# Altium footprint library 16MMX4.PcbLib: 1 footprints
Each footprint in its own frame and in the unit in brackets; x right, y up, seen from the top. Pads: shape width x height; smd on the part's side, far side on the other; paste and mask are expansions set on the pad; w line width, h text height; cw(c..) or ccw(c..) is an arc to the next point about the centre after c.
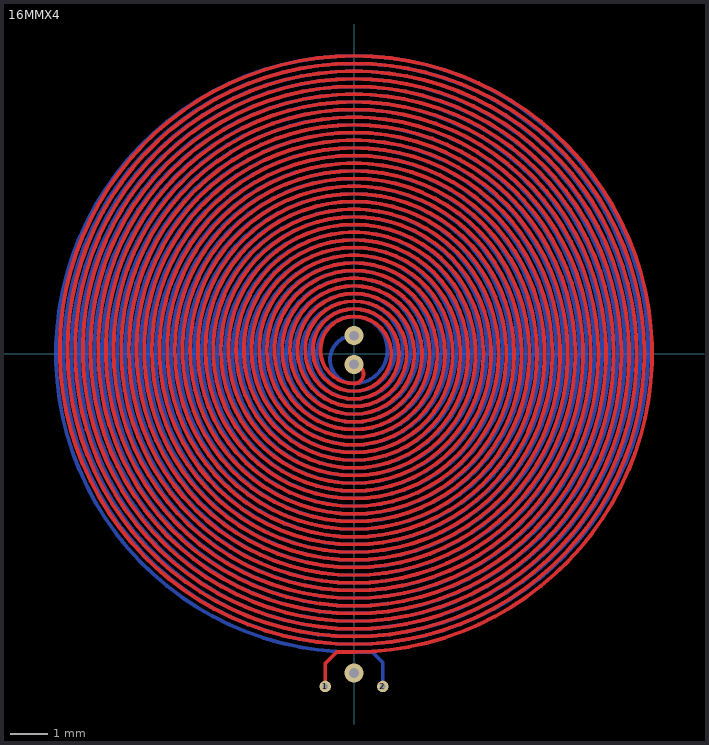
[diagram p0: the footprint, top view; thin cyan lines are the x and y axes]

## 16MMX4 [mil] "4,4,70,20,10,35"
pads (2):
  round 12 hole 6: 1(-30,-347) 2(30,-347)
via 0,19 diameter 20 hole 10
via 0,-11 diameter 20 hole 10
via 0,-333 diameter 20 hole 10
Top Layer:
  lines w4: -30,-347 -30,-344.65 ; -30,-344.65 -30,-344.25 ; -30,-344.65 -30,-344.25 ; -30,-344.25 -30,-323 ; -30,-344.25 -30,-323 ; -30,-323 -18,-311 ; -18,-311 0,-311 ; -18,-311 0,-311 ; 0,-311 ccw(c0,0) 0,311 ; 0,-311 ccw(c0,0) 0,311 ; 0,-311 0,-311 ; 0,-303 cw(c0,4) 0,311 ; 0,-303 ccw(c0,0) 0,303 ; 0,-303 ccw(c0,0) 0,303 ; 0,-303 cw(c0,4) 0,311 ; 0,-295 cw(c0,4) 0,303 ; 0,-295 ccw(c0,0) 0,295 ; 0,-295 ccw(c0,0) 0,295 ; 0,-295 cw(c0,4) 0,303 ; 0,-287 cw(c0,4) 0,295 ; 0,-287 ccw(c0,0) 0,287 ; 0,-287 ccw(c0,0) 0,287 ; 0,-287 cw(c0,4) 0,295 ; 0,-279 cw(c0,4) 0,287 ; 0,-279 ccw(c0,0) 0,279 ; 0,-279 ccw(c0,0) 0,279 ; 0,-279 cw(c0,4) 0,287 ; 0,-271 cw(c0,4) 0,279 ; 0,-271 ccw(c0,0) 0,271 ; 0,-271 ccw(c0,0) 0,271 ; 0,-271 cw(c0,4) 0,279 ; 0,-263 cw(c0,4) 0,271 ; 0,-263 ccw(c0,0) 0,263 ; 0,-263 ccw(c0,0) 0,263 ; 0,-263 cw(c0,4) 0,271 ; 0,-255 cw(c0,4) 0,263 ; 0,-255 ccw(c0,0) 0,255 ; 0,-255 ccw(c0,0) 0,255 ; 0,-255 cw(c0,4) 0,263 ; 0,-247 cw(c0,4) 0,255 ; 0,-247 ccw(c0,0) 0,247 ; 0,-247 ccw(c0,0) 0,247 ; 0,-247 cw(c0,4) 0,255 ; 0,-239 cw(c0,4) 0,247 ; 0,-239 ccw(c0,0) 0,239 ; 0,-239 ccw(c0,0) 0,239 ; 0,-239 cw(c0,4) 0,247 ; 0,-231 cw(c0,4) 0,239 ; 0,-231 ccw(c0,0) 0,231 ; 0,-231 ccw(c0,0) 0,231 ; 0,-231 cw(c0,4) 0,239 ; 0,-223 cw(c0,4) 0,231 ; 0,-223 ccw(c0,0) 0,223 ; 0,-223 ccw(c0,0) 0,223 ; 0,-223 cw(c0,4) 0,231 ; 0,-215 cw(c0,4) 0,223 ; 0,-215 ccw(c0,0) 0,215 ; 0,-215 ccw(c0,0) 0,215 ; 0,-215 cw(c0,4) 0,223 ; 0,-207 cw(c0,4) 0,215 ; 0,-207 ccw(c0,0) 0,207 ; 0,-207 ccw(c0,0) 0,207 ; 0,-207 cw(c0,4) 0,215 ; 0,-199 cw(c0,4) 0,207 ; 0,-199 ccw(c0,0) 0,199 ; 0,-199 ccw(c0,0) 0,199 ; 0,-199 cw(c0,4) 0,207 ; 0,-191 cw(c0,4) 0,199 ; 0,-191 ccw(c0,0) 0,191 ; 0,-191 ccw(c0,0) 0,191 ; 0,-191 cw(c0,4) 0,199 ; 0,-183 cw(c0,4) 0,191 ; 0,-183 ccw(c0,0) 0,183 ; 0,-183 ccw(c0,0) 0,183 ; 0,-183 cw(c0,4) 0,191 ; 0,-175 cw(c0,4) 0,183 ; 0,-175 ccw(c0,0) 0,175 ; 0,-175 ccw(c0,0) 0,175 ; 0,-175 cw(c0,4) 0,183 ; 0,-167 cw(c0,4) 0,175 ; 0,-167 ccw(c0,0) 0,167 ; 0,-167 ccw(c0,0) 0,167 ; 0,-167 cw(c0,4) 0,175 ; 0,-159 cw(c0,4) 0,167 ; 0,-159 ccw(c0,0) 0,159 ; 0,-159 ccw(c0,0) 0,159 ; 0,-159 cw(c0,4) 0,167 ; 0,-151 cw(c0,4) 0,159 ; 0,-151 ccw(c0,0) 0,151 ; 0,-151 ccw(c0,0) 0,151 ; 0,-151 cw(c0,4) 0,159 ; 0,-143 cw(c0,4) 0,151 ; 0,-143 ccw(c0,0) 0,143 ; 0,-143 ccw(c0,0) 0,143 ; 0,-143 cw(c0,4) 0,151 ; 0,-135 cw(c0,4) 0,143 ; 0,-135 ccw(c0,0) 0,135 ; 0,-135 ccw(c0,0) 0,135 ; 0,-135 cw(c0,4) 0,143 ; 0,-127 cw(c0,4) 0,135 ; 0,-127 ccw(c0,0) 0,127 ; 0,-127 ccw(c0,0) 0,127 ; 0,-127 cw(c0,4) 0,135 ; 0,-119 cw(c0,4) 0,127 ; 0,-119 ccw(c0,0) 0,119 ; 0,-119 ccw(c0,0) 0,119 ; 0,-119 cw(c0,4) 0,127 ; 0,-111 cw(c0,4) 0,119 ; 0,-111 ccw(c0,0) 0,111 ; 0,-111 ccw(c0,0) 0,111 ; 0,-111 cw(c0,4) 0,119 ; 0,-103 cw(c0,4) 0,111 ; 0,-103 ccw(c0,0) 0,103 ; 0,-103 ccw(c0,0) 0,103 ; 0,-103 cw(c0,4) 0,111 ; 0,-95 cw(c0,4) 0,103 ; 0,-95 ccw(c0,0) 0,95 ; 0,-95 ccw(c0,0) 0,95 ; 0,-95 cw(c0,4) 0,103 ; 0,-87 cw(c0,4) 0,95 ; 0,-87 ccw(c0,0) 0,87 ; 0,-87 ccw(c0,0) 0,87 ; 0,-87 cw(c0,4) 0,95 ; 0,-79 cw(c0,4) 0,87 ; 0,-79 ccw(c0,0) 0,79 ; 0,-79 ccw(c0,0) 0,79 ; 0,-79 cw(c0,4) 0,87 ; 0,-71 cw(c0,4) 0,79 ; 0,-71 ccw(c0,0) 0,71 ; 0,-71 ccw(c0,0) 0,71 ; 0,-71 cw(c0,4) 0,79 ; 0,-63 cw(c0,4) 0,71 ; 0,-63 ccw(c0,0) 0,63 ; 0,-63 ccw(c0,0) 0,63 ; 0,-63 cw(c0,4) 0,71 ; 0,-55 cw(c0,4) 0,63 ; 0,-55 ccw(c0,0) 0,55 ; 0,-55 ccw(c0,0) 0,55 ; 0,-55 cw(c0,4) 0,63 ; 0,-47 cw(c0,4) 0,55 ; 0,-47 ccw(c0,0) 0,47 ; 0,-47 ccw(c0,0) 0,47 ; 0,-47 cw(c0,4) 0,55 ; 0,-39 cw(c0,4) 0,47 ; 0,-39 ccw(c0,0) 0,39 ; 0,-39 ccw(c0,0) 0,39 ; 0,-39 cw(c0,4) 0,47 ; 0,-31 cw(c0,4) 0,39 ; 0,-31 ccw(c0,-21) 0,-11 cw(c0,-21) 0,-31 ; 0,-31 cw(c0,4) 0,39
Mid-Layer 1:
  lines w4: 0,-311 cw(c0,0) 0,311 ; 0,-311 cw(c0,0) 0,311 ; 0,-311 0,-333 0,-311 ; 0,-303 cw(c0,0) 0,303 ; 0,-303 ccw(c0,4) 0,311 ; 0,-303 ccw(c0,4) 0,311 ; 0,-303 cw(c0,0) 0,303 ; 0,-295 cw(c0,0) 0,295 ; 0,-295 ccw(c0,4) 0,303 ; 0,-295 ccw(c0,4) 0,303 ; 0,-295 cw(c0,0) 0,295 ; 0,-287 cw(c0,0) 0,287 ; 0,-287 ccw(c0,4) 0,295 ; 0,-287 ccw(c0,4) 0,295 ; 0,-287 cw(c0,0) 0,287 ; 0,-279 cw(c0,0) 0,279 ; 0,-279 ccw(c0,4) 0,287 ; 0,-279 ccw(c0,4) 0,287 ; 0,-279 cw(c0,0) 0,279 ; 0,-271 cw(c0,0) 0,271 ; 0,-271 ccw(c0,4) 0,279 ; 0,-271 ccw(c0,4) 0,279 ; 0,-271 cw(c0,0) 0,271 ; 0,-263 cw(c0,0) 0,263 ; 0,-263 ccw(c0,4) 0,271 ; 0,-263 ccw(c0,4) 0,271 ; 0,-263 cw(c0,0) 0,263 ; 0,-255 cw(c0,0) 0,255 ; 0,-255 ccw(c0,4) 0,263 ; 0,-255 ccw(c0,4) 0,263 ; 0,-255 cw(c0,0) 0,255 ; 0,-247 cw(c0,0) 0,247 ; 0,-247 ccw(c0,4) 0,255 ; 0,-247 ccw(c0,4) 0,255 ; 0,-247 cw(c0,0) 0,247 ; 0,-239 cw(c0,0) 0,239 ; 0,-239 ccw(c0,4) 0,247 ; 0,-239 ccw(c0,4) 0,247 ; 0,-239 cw(c0,0) 0,239 ; 0,-231 cw(c0,0) 0,231 ; 0,-231 ccw(c0,4) 0,239 ; 0,-231 ccw(c0,4) 0,239 ; 0,-231 cw(c0,0) 0,231 ; 0,-223 cw(c0,0) 0,223 ; 0,-223 ccw(c0,4) 0,231 ; 0,-223 ccw(c0,4) 0,231 ; 0,-223 cw(c0,0) 0,223 ; 0,-215 cw(c0,0) 0,215 ; 0,-215 ccw(c0,4) 0,223 ; 0,-215 ccw(c0,4) 0,223 ; 0,-215 cw(c0,0) 0,215 ; 0,-207 cw(c0,0) 0,207 ; 0,-207 ccw(c0,4) 0,215 ; 0,-207 ccw(c0,4) 0,215 ; 0,-207 cw(c0,0) 0,207 ; 0,-199 cw(c0,0) 0,199 ; 0,-199 ccw(c0,4) 0,207 ; 0,-199 ccw(c0,4) 0,207 ; 0,-199 cw(c0,0) 0,199 ; 0,-191 cw(c0,0) 0,191 ; 0,-191 ccw(c0,4) 0,199 ; 0,-191 ccw(c0,4) 0,199 ; 0,-191 cw(c0,0) 0,191 ; 0,-183 cw(c0,0) 0,183 ; 0,-183 ccw(c0,4) 0,191 ; 0,-183 ccw(c0,4) 0,191 ; 0,-183 cw(c0,0) 0,183 ; 0,-175 cw(c0,0) 0,175 ; 0,-175 ccw(c0,4) 0,183 ; 0,-175 ccw(c0,4) 0,183 ; 0,-175 cw(c0,0) 0,175 ; 0,-167 cw(c0,0) 0,167 ; 0,-167 ccw(c0,4) 0,175 ; 0,-167 ccw(c0,4) 0,175 ; 0,-167 cw(c0,0) 0,167 ; 0,-159 cw(c0,0) 0,159 ; 0,-159 ccw(c0,4) 0,167 ; 0,-159 ccw(c0,4) 0,167 ; 0,-159 cw(c0,0) 0,159 ; 0,-151 cw(c0,0) 0,151 ; 0,-151 ccw(c0,4) 0,159 ; 0,-151 ccw(c0,4) 0,159 ; 0,-151 cw(c0,0) 0,151 ; 0,-143 cw(c0,0) 0,143 ; 0,-143 ccw(c0,4) 0,151 ; 0,-143 ccw(c0,4) 0,151 ; 0,-143 cw(c0,0) 0,143 ; 0,-135 cw(c0,0) 0,135 ; 0,-135 ccw(c0,4) 0,143 ; 0,-135 ccw(c0,4) 0,143 ; 0,-135 cw(c0,0) 0,135 ; 0,-127 cw(c0,0) 0,127 ; 0,-127 ccw(c0,4) 0,135 ; 0,-127 ccw(c0,4) 0,135 ; 0,-127 cw(c0,0) 0,127 ; 0,-119 cw(c0,0) 0,119 ; 0,-119 ccw(c0,4) 0,127 ; 0,-119 ccw(c0,4) 0,127 ; 0,-119 cw(c0,0) 0,119 ; 0,-111 cw(c0,0) 0,111 ; 0,-111 ccw(c0,4) 0,119 ; 0,-111 ccw(c0,4) 0,119 ; 0,-111 cw(c0,0) 0,111 ; 0,-103 cw(c0,0) 0,103 ; 0,-103 ccw(c0,4) 0,111 ; 0,-103 ccw(c0,4) 0,111 ; 0,-103 cw(c0,0) 0,103 ; 0,-95 cw(c0,0) 0,95 ; 0,-95 ccw(c0,4) 0,103 ; 0,-95 ccw(c0,4) 0,103 ; 0,-95 cw(c0,0) 0,95 ; 0,-87 cw(c0,0) 0,87 ; 0,-87 ccw(c0,4) 0,95 ; 0,-87 ccw(c0,4) 0,95 ; 0,-87 cw(c0,0) 0,87 ; 0,-79 cw(c0,0) 0,79 ; 0,-79 ccw(c0,4) 0,87 ; 0,-79 ccw(c0,4) 0,87 ; 0,-79 cw(c0,0) 0,79 ; 0,-71 cw(c0,0) 0,71 ; 0,-71 ccw(c0,4) 0,79 ; 0,-71 ccw(c0,4) 0,79 ; 0,-71 cw(c0,0) 0,71 ; 0,-63 cw(c0,0) 0,63 ; 0,-63 ccw(c0,4) 0,71 ; 0,-63 ccw(c0,4) 0,71 ; 0,-63 cw(c0,0) 0,63 ; 0,-55 cw(c0,0) 0,55 ; 0,-55 ccw(c0,4) 0,63 ; 0,-55 ccw(c0,4) 0,63 ; 0,-55 cw(c0,0) 0,55 ; 0,-47 cw(c0,0) 0,47 ; 0,-47 ccw(c0,4) 0,55 ; 0,-47 ccw(c0,4) 0,55 ; 0,-47 cw(c0,0) 0,47 ; 0,-39 cw(c0,0) 0,39 ; 0,-39 ccw(c0,4) 0,47 ; 0,-39 ccw(c0,4) 0,47 ; 0,-39 cw(c0,0) 0,39 ; 0,-31 cw(c0,-21) 0,-11 ccw(c0,-21) 0,-31 ; 0,-31 ccw(c0,4) 0,39 ; 0,-31 ccw(c0,4) 0,39
Mid-Layer 2:
  lines w4: 0,-311 ccw(c0,0) 0,311 ; 0,-311 ccw(c0,0) 0,311 ; 0,-311 0,-333 0,-311 ; 0,-303 cw(c0,4) 0,311 ; 0,-303 ccw(c0,0) 0,303 ; 0,-303 ccw(c0,0) 0,303 ; 0,-303 cw(c0,4) 0,311 ; 0,-295 cw(c0,4) 0,303 ; 0,-295 ccw(c0,0) 0,295 ; 0,-295 ccw(c0,0) 0,295 ; 0,-295 cw(c0,4) 0,303 ; 0,-287 cw(c0,4) 0,295 ; 0,-287 ccw(c0,0) 0,287 ; 0,-287 ccw(c0,0) 0,287 ; 0,-287 cw(c0,4) 0,295 ; 0,-279 cw(c0,4) 0,287 ; 0,-279 ccw(c0,0) 0,279 ; 0,-279 ccw(c0,0) 0,279 ; 0,-279 cw(c0,4) 0,287 ; 0,-271 cw(c0,4) 0,279 ; 0,-271 ccw(c0,0) 0,271 ; 0,-271 ccw(c0,0) 0,271 ; 0,-271 cw(c0,4) 0,279 ; 0,-263 cw(c0,4) 0,271 ; 0,-263 ccw(c0,0) 0,263 ; 0,-263 ccw(c0,0) 0,263 ; 0,-263 cw(c0,4) 0,271 ; 0,-255 cw(c0,4) 0,263 ; 0,-255 ccw(c0,0) 0,255 ; 0,-255 ccw(c0,0) 0,255 ; 0,-255 cw(c0,4) 0,263 ; 0,-247 cw(c0,4) 0,255 ; 0,-247 ccw(c0,0) 0,247 ; 0,-247 ccw(c0,0) 0,247 ; 0,-247 cw(c0,4) 0,255 ; 0,-239 cw(c0,4) 0,247 ; 0,-239 ccw(c0,0) 0,239 ; 0,-239 ccw(c0,0) 0,239 ; 0,-239 cw(c0,4) 0,247 ; 0,-231 cw(c0,4) 0,239 ; 0,-231 ccw(c0,0) 0,231 ; 0,-231 ccw(c0,0) 0,231 ; 0,-231 cw(c0,4) 0,239 ; 0,-223 cw(c0,4) 0,231 ; 0,-223 ccw(c0,0) 0,223 ; 0,-223 ccw(c0,0) 0,223 ; 0,-223 cw(c0,4) 0,231 ; 0,-215 cw(c0,4) 0,223 ; 0,-215 ccw(c0,0) 0,215 ; 0,-215 ccw(c0,0) 0,215 ; 0,-215 cw(c0,4) 0,223 ; 0,-207 cw(c0,4) 0,215 ; 0,-207 ccw(c0,0) 0,207 ; 0,-207 ccw(c0,0) 0,207 ; 0,-207 cw(c0,4) 0,215 ; 0,-199 cw(c0,4) 0,207 ; 0,-199 ccw(c0,0) 0,199 ; 0,-199 ccw(c0,0) 0,199 ; 0,-199 cw(c0,4) 0,207 ; 0,-191 cw(c0,4) 0,199 ; 0,-191 ccw(c0,0) 0,191 ; 0,-191 ccw(c0,0) 0,191 ; 0,-191 cw(c0,4) 0,199 ; 0,-183 cw(c0,4) 0,191 ; 0,-183 ccw(c0,0) 0,183 ; 0,-183 ccw(c0,0) 0,183 ; 0,-183 cw(c0,4) 0,191 ; 0,-175 cw(c0,4) 0,183 ; 0,-175 ccw(c0,0) 0,175 ; 0,-175 ccw(c0,0) 0,175 ; 0,-175 cw(c0,4) 0,183 ; 0,-167 cw(c0,4) 0,175 ; 0,-167 ccw(c0,0) 0,167 ; 0,-167 ccw(c0,0) 0,167 ; 0,-167 cw(c0,4) 0,175 ; 0,-159 cw(c0,4) 0,167 ; 0,-159 ccw(c0,0) 0,159 ; 0,-159 ccw(c0,0) 0,159 ; 0,-159 cw(c0,4) 0,167 ; 0,-151 cw(c0,4) 0,159 ; 0,-151 ccw(c0,0) 0,151 ; 0,-151 ccw(c0,0) 0,151 ; 0,-151 cw(c0,4) 0,159 ; 0,-143 cw(c0,4) 0,151 ; 0,-143 ccw(c0,0) 0,143 ; 0,-143 ccw(c0,0) 0,143 ; 0,-143 cw(c0,4) 0,151 ; 0,-135 cw(c0,4) 0,143 ; 0,-135 ccw(c0,0) 0,135 ; 0,-135 ccw(c0,0) 0,135 ; 0,-135 cw(c0,4) 0,143 ; 0,-127 cw(c0,4) 0,135 ; 0,-127 ccw(c0,0) 0,127 ; 0,-127 ccw(c0,0) 0,127 ; 0,-127 cw(c0,4) 0,135 ; 0,-119 cw(c0,4) 0,127 ; 0,-119 ccw(c0,0) 0,119 ; 0,-119 ccw(c0,0) 0,119 ; 0,-119 cw(c0,4) 0,127 ; 0,-111 cw(c0,4) 0,119 ; 0,-111 ccw(c0,0) 0,111 ; 0,-111 ccw(c0,0) 0,111 ; 0,-111 cw(c0,4) 0,119 ; 0,-103 cw(c0,4) 0,111 ; 0,-103 ccw(c0,0) 0,103 ; 0,-103 ccw(c0,0) 0,103 ; 0,-103 cw(c0,4) 0,111 ; 0,-95 cw(c0,4) 0,103 ; 0,-95 ccw(c0,0) 0,95 ; 0,-95 ccw(c0,0) 0,95 ; 0,-95 cw(c0,4) 0,103 ; 0,-87 cw(c0,4) 0,95 ; 0,-87 ccw(c0,0) 0,87 ; 0,-87 ccw(c0,0) 0,87 ; 0,-87 cw(c0,4) 0,95 ; 0,-79 cw(c0,4) 0,87 ; 0,-79 ccw(c0,0) 0,79 ; 0,-79 ccw(c0,0) 0,79 ; 0,-79 cw(c0,4) 0,87 ; 0,-71 cw(c0,4) 0,79 ; 0,-71 ccw(c0,0) 0,71 ; 0,-71 ccw(c0,0) 0,71 ; 0,-71 cw(c0,4) 0,79 ; 0,-63 cw(c0,4) 0,71 ; 0,-63 ccw(c0,0) 0,63 ; 0,-63 ccw(c0,0) 0,63 ; 0,-63 cw(c0,4) 0,71 ; 0,-55 cw(c0,4) 0,63 ; 0,-55 ccw(c0,0) 0,55 ; 0,-55 ccw(c0,0) 0,55 ; 0,-55 cw(c0,4) 0,63 ; 0,-47 cw(c0,4) 0,55 ; 0,-47 ccw(c0,0) 0,47 ; 0,-47 ccw(c0,0) 0,47 ; 0,-47 cw(c0,4) 0,55 ; 0,-39 cw(c0,4) 0,47 ; 0,-39 ccw(c0,0) 0,39 ; 0,-39 ccw(c0,0) 0,39 ; 0,-39 cw(c0,4) 0,47 ; 0,-31 cw(c0,4) 0,39 ; 0,-31 ccw(c0,-6) 0,19 cw(c0,-6) 0,-31 ; 0,-31 cw(c0,4) 0,39
Bottom Layer:
  lines w4: 30,-347 30,-322 19,-311 ; 0,-311 cw(c0,0) 0,311 ; 0,-311 cw(c0,0) 0,311 ; 0,-311 0,-311 ; 0,-311 19,-311 ; 0,-311 19,-311 ; 0,-303 cw(c0,0) 0,303 ; 0,-303 ccw(c0,4) 0,311 ; 0,-303 ccw(c0,4) 0,311 ; 0,-303 cw(c0,0) 0,303 ; 0,-295 cw(c0,0) 0,295 ; 0,-295 ccw(c0,4) 0,303 ; 0,-295 ccw(c0,4) 0,303 ; 0,-295 cw(c0,0) 0,295 ; 0,-287 cw(c0,0) 0,287 ; 0,-287 ccw(c0,4) 0,295 ; 0,-287 ccw(c0,4) 0,295 ; 0,-287 cw(c0,0) 0,287 ; 0,-279 cw(c0,0) 0,279 ; 0,-279 ccw(c0,4) 0,287 ; 0,-279 ccw(c0,4) 0,287 ; 0,-279 cw(c0,0) 0,279 ; 0,-271 cw(c0,0) 0,271 ; 0,-271 ccw(c0,4) 0,279 ; 0,-271 ccw(c0,4) 0,279 ; 0,-271 cw(c0,0) 0,271 ; 0,-263 cw(c0,0) 0,263 ; 0,-263 ccw(c0,4) 0,271 ; 0,-263 ccw(c0,4) 0,271 ; 0,-263 cw(c0,0) 0,263 ; 0,-255 cw(c0,0) 0,255 ; 0,-255 ccw(c0,4) 0,263 ; 0,-255 ccw(c0,4) 0,263 ; 0,-255 cw(c0,0) 0,255 ; 0,-247 cw(c0,0) 0,247 ; 0,-247 ccw(c0,4) 0,255 ; 0,-247 ccw(c0,4) 0,255 ; 0,-247 cw(c0,0) 0,247 ; 0,-239 cw(c0,0) 0,239 ; 0,-239 ccw(c0,4) 0,247 ; 0,-239 ccw(c0,4) 0,247 ; 0,-239 cw(c0,0) 0,239 ; 0,-231 cw(c0,0) 0,231 ; 0,-231 ccw(c0,4) 0,239 ; 0,-231 ccw(c0,4) 0,239 ; 0,-231 cw(c0,0) 0,231 ; 0,-223 cw(c0,0) 0,223 ; 0,-223 ccw(c0,4) 0,231 ; 0,-223 ccw(c0,4) 0,231 ; 0,-223 cw(c0,0) 0,223 ; 0,-215 cw(c0,0) 0,215 ; 0,-215 ccw(c0,4) 0,223 ; 0,-215 ccw(c0,4) 0,223 ; 0,-215 cw(c0,0) 0,215 ; 0,-207 cw(c0,0) 0,207 ; 0,-207 ccw(c0,4) 0,215 ; 0,-207 ccw(c0,4) 0,215 ; 0,-207 cw(c0,0) 0,207 ; 0,-199 cw(c0,0) 0,199 ; 0,-199 ccw(c0,4) 0,207 ; 0,-199 ccw(c0,4) 0,207 ; 0,-199 cw(c0,0) 0,199 ; 0,-191 cw(c0,0) 0,191 ; 0,-191 ccw(c0,4) 0,199 ; 0,-191 ccw(c0,4) 0,199 ; 0,-191 cw(c0,0) 0,191 ; 0,-183 cw(c0,0) 0,183 ; 0,-183 ccw(c0,4) 0,191 ; 0,-183 ccw(c0,4) 0,191 ; 0,-183 cw(c0,0) 0,183 ; 0,-175 cw(c0,0) 0,175 ; 0,-175 ccw(c0,4) 0,183 ; 0,-175 ccw(c0,4) 0,183 ; 0,-175 cw(c0,0) 0,175 ; 0,-167 cw(c0,0) 0,167 ; 0,-167 ccw(c0,4) 0,175 ; 0,-167 ccw(c0,4) 0,175 ; 0,-167 cw(c0,0) 0,167 ; 0,-159 cw(c0,0) 0,159 ; 0,-159 ccw(c0,4) 0,167 ; 0,-159 ccw(c0,4) 0,167 ; 0,-159 cw(c0,0) 0,159 ; 0,-151 cw(c0,0) 0,151 ; 0,-151 ccw(c0,4) 0,159 ; 0,-151 ccw(c0,4) 0,159 ; 0,-151 cw(c0,0) 0,151 ; 0,-143 cw(c0,0) 0,143 ; 0,-143 ccw(c0,4) 0,151 ; 0,-143 ccw(c0,4) 0,151 ; 0,-143 cw(c0,0) 0,143 ; 0,-135 cw(c0,0) 0,135 ; 0,-135 ccw(c0,4) 0,143 ; 0,-135 ccw(c0,4) 0,143 ; 0,-135 cw(c0,0) 0,135 ; 0,-127 cw(c0,0) 0,127 ; 0,-127 ccw(c0,4) 0,135 ; 0,-127 ccw(c0,4) 0,135 ; 0,-127 cw(c0,0) 0,127 ; 0,-119 cw(c0,0) 0,119 ; 0,-119 ccw(c0,4) 0,127 ; 0,-119 ccw(c0,4) 0,127 ; 0,-119 cw(c0,0) 0,119 ; 0,-111 cw(c0,0) 0,111 ; 0,-111 ccw(c0,4) 0,119 ; 0,-111 ccw(c0,4) 0,119 ; 0,-111 cw(c0,0) 0,111 ; 0,-103 cw(c0,0) 0,103 ; 0,-103 ccw(c0,4) 0,111 ; 0,-103 ccw(c0,4) 0,111 ; 0,-103 cw(c0,0) 0,103 ; 0,-95 cw(c0,0) 0,95 ; 0,-95 ccw(c0,4) 0,103 ; 0,-95 ccw(c0,4) 0,103 ; 0,-95 cw(c0,0) 0,95 ; 0,-87 cw(c0,0) 0,87 ; 0,-87 ccw(c0,4) 0,95 ; 0,-87 ccw(c0,4) 0,95 ; 0,-87 cw(c0,0) 0,87 ; 0,-79 cw(c0,0) 0,79 ; 0,-79 ccw(c0,4) 0,87 ; 0,-79 ccw(c0,4) 0,87 ; 0,-79 cw(c0,0) 0,79 ; 0,-71 cw(c0,0) 0,71 ; 0,-71 ccw(c0,4) 0,79 ; 0,-71 ccw(c0,4) 0,79 ; 0,-71 cw(c0,0) 0,71 ; 0,-63 cw(c0,0) 0,63 ; 0,-63 ccw(c0,4) 0,71 ; 0,-63 ccw(c0,4) 0,71 ; 0,-63 cw(c0,0) 0,63 ; 0,-55 cw(c0,0) 0,55 ; 0,-55 ccw(c0,4) 0,63 ; 0,-55 ccw(c0,4) 0,63 ; 0,-55 cw(c0,0) 0,55 ; 0,-47 cw(c0,0) 0,47 ; 0,-47 ccw(c0,4) 0,55 ; 0,-47 ccw(c0,4) 0,55 ; 0,-47 cw(c0,0) 0,47 ; 0,-39 cw(c0,0) 0,39 ; 0,-39 ccw(c0,4) 0,47 ; 0,-39 ccw(c0,4) 0,47 ; 0,-39 cw(c0,0) 0,39 ; 0,-31 cw(c0,-6) 0,19 ccw(c0,-6) 0,-31 ; 0,-31 ccw(c0,4) 0,39 ; 0,-31 ccw(c0,4) 0,39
